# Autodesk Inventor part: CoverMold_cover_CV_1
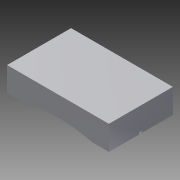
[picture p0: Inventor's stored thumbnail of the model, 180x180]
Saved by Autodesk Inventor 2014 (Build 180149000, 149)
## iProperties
Created: 2009-12
Part Number: CoverMold_cover_CV_1
Document SubType Name: Modeling
Designer: gaom
Density: 1 g/cm^3
Material: Generic
Appearance: Default
Author: gaom
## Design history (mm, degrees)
node "CoverMold_cover_CV_Base"
feature "Solid1::CoverMold_cover_CV_Base"
tag "TaggingFeature1"
body "Solid1"
